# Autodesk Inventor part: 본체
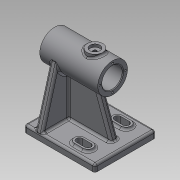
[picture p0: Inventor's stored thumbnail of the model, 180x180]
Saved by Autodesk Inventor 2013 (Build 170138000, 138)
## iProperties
Created: 2019-10
Part Number: 본체
Material: 일반
Document SubType Name: Modeling
Designer: Administrator
Density: 1 g/cm^3
Author: Administrator
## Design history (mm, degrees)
sketch "스케치1"
  geometry: L1 (-50, 43)-(50, 43); L2 (50, 43)-(50, -43); L3 (50, -43)-(-50, -43); L4 (-50, -43)-(-50, 43); L5 (-50, 43)-(50, -43); L6 (50, 43)-(-50, -43); 1 further point
  constraints: 12 end point, 2 midpoint, 2 parallel, 1 horizontal, 1 perpendicular
  dimensions: "d0" = 100 distance of L1.start L1.end; "d2" = 86 distance of L1.end L2.end
extrude "돌출1" new body sketch "스케치1" distance "d3" = 10; taper "d4" = 0 deg
sketch "스케치2"
  geometry: L1 (50, 0)-(-50, 0) reference; L2 (-32, 86)-(-32, 107); L3 (-32, 107)-(50, 107); L4 (50, 107)-(50, 86); L5 (-32, 86)-(50, 86); 2 further points
  constraints: 8 end point, 2 perpendicular, 1 midpoint, 1 parallel, 1 vertical alignment
  dimensions: "d9" = 82 distance of L2.end L3.end; "d10" = 42 diameter of L3 L5; "d11" = 172 diameter of L1 L5
revolve "회전1" sketch "스케치2" stored, may be unused: angle "d12" = 90 deg
sketch "스케치3"
  geometry: L1 (50, 10)-(50, 0) reference; L2 (50, 0)-(-50, 0) reference; L3 (-50, 0)-(-50, 10) reference; L4 (-50, 10)-(50, 10) reference; L5 (50, 65)-(-32, 65) reference; L6 (-32, 65)-(-32, 107) reference; L7 (-32, 107)-(50, 107) reference; L8 (50, 107)-(50, 65) reference; L9 (-32, 86)-(50, 86); L10 (-32, 100.5)-(30, 100.5); L11 (30, 100.5)-(30, 97.5); L12 (30, 97.5)-(50, 97.5); 1 further point
  constraints: 8 end point, 2 midpoint, 2 perpendicular, 2 point on line, 1 parallel
  dimensions: "d13" = 23 diameter of L12 L9; "d15" = 29 diameter of L10 L9; "d16" = 62 distance of L10.start L10.end
revolve "회전2" sketch "스케치3" stored, may be unused: angle "d17" = 90 deg
node "작업 평면1"
sketch "스케치4"
  geometry: L1 (-50, -43)-(-50, 43) reference; L2 (-32, -21)-(-32, 21) reference; C1 r 11 at (-7, 0); 2 further points
  constraints: 1 centre point, 1 horizontal alignment, 1 midpoint
  dimensions: "d20" = 22 diameter of C1; "d21" = 25 distance from line of L2 C1.centre
extrude "돌출2" join sketch "스케치4" stored distance "d22" = 10; taper "d23" = 0 deg
sketch "스케치5"
  geometry: C1 r 11 at (0, 0) reference
hole "구멍1" sketch "스케치5" at (0, 0) diameter "d24" = 4.917; stored, may be unused: countersink angle "d28" = 90 deg, drill point angle "d30" = 118 deg; dims "d25" = 6, "d26" = 14, "d27" = 4, "d29" = 8
sketch "스케치6"
  geometry: C1 r 14.5 at (0, 0) reference; 2 further points
  constraints: 1 horizontal alignment
  dimensions: "d31" = 18 distance of C1.centre point (-18, 0)
hole "구멍2" sketch "스케치6" at (-18, 0) diameter "d32" = 2.459; stored, may be unused: countersink angle "d36" = 90 deg, drill point angle "d38" = 118 deg; dims "d33" = 8, "d34" = 14, "d35" = 4, "d37" = 10
sketch "스케치7"
  geometry: C1 r 11.5 at (0, 0) reference; 2 further points
  constraints: 1 vertical alignment
  dimensions: "d42" = 18 distance of C1.centre point (0, 18)
hole "구멍3" sketch "스케치7" at (0, 18) diameter "d43" = 2.459; stored, may be unused: countersink angle "d47" = 90 deg, drill point angle "d49" = 118 deg; dims "d44" = 8, "d45" = 14, "d46" = 4, "d48" = 10
fillet "모깎기1" dims "d53" = 3
node "작업 평면2"
sketch "스케치9"
  geometry: L1 (10, 83)-(10, 3) reference; L2 (7, 0)-(0, 0) reference; L3 (0, 0)-(0, 86) reference; L4 (0, 86)-(7, 86) reference; L5 (7, 86)-(86, 64); L6 (7, 0)-(86, 22); C1 r 11.5 at (86, 43) reference; A1 r 3 centre (7, 83) between (10, 83) and (7, 86) reference; A2 r 3 centre (7, 3) between (7, 0) and (10, 3) reference; A3 r 21 centre (86, 43) between (86, 64) and (86, 22) reference; 1 further point
  constraints: 4 end point, 2 point on circle, 2 vertical alignment
extrude "돌출3" join sketch "스케치9" distance "d55" = 10; taper "d56" = 0 deg
sketch "스케치10"
  geometry: L1 (-32, 107)-(-18, 107) reference; L2 (-18, 107)-(-18, 110) reference; L3 (-18, 110)-(-14, 110) reference; L4 (-14, 110)-(-14, 106) reference; L5 (-14, 106)-(-9.459, 106) reference; L6 (-9.459, 106)-(-9.459, 100.5) reference; L7 (-9.459, 100.5)-(-32, 100.5) reference; L8 (-32, 100.5)-(-32, 102.77) reference; L9 (-32, 102.77)-(-22, 102.77) reference; L10 (-22, 102.77)-(-21.261, 104) reference; L11 (-21.261, 104)-(-22, 105.229) reference; L12 (-22, 105.229)-(-32, 105.229) reference; L13 (-32, 105.229)-(-32, 107) reference; L14 (50, 97.5)-(30, 97.5) reference; L15 (30, 97.5)-(30, 100.5) reference; L16 (30, 100.5)-(-4.542, 100.5) reference; L17 (-4.542, 100.5)-(-4.542, 106) reference; L18 (-4.542, 106)-(0, 106) reference; L19 (0, 106)-(0, 110) reference; L20 (0, 110)-(4, 110) reference; L21 (4, 110)-(4, 107) reference; L22 (4, 107)-(50, 107) reference; L23 (50, 107)-(50, 105.229) reference; L24 (50, 105.229)-(40, 105.229) reference; L25 (40, 105.229)-(39.261, 104) reference; L26 (39.261, 104)-(40, 102.77) reference; L27 (40, 102.77)-(50, 102.77) reference; L28 (50, 102.77)-(50, 97.5) reference; L29 (-47, 10)-(25, 10) reference; L30 (25, 10)-(25, 65) reference; L31 (25, 65)-(-32, 65) reference; L32 (-32, 65)-(-32, 66.77) reference; L33 (-32, 66.77)-(-22, 66.77) reference; L34 (-22, 66.77)-(-21.261, 68) reference; L35 (-21.261, 68)-(-22, 69.229) reference; L36 (-22, 69.229)-(-32, 69.229) reference; L37 (-32, 69.229)-(-32, 71.5) reference; L38 (-32, 71.5)-(30, 71.5) reference; L39 (30, 71.5)-(30, 74.5) reference; L40 (30, 74.5)-(50, 74.5) reference; L41 (50, 74.5)-(50, 69.229) reference; L42 (50, 69.229)-(40, 69.229) reference; L43 (40, 69.229)-(39.261, 68) reference; L44 (39.261, 68)-(40, 66.77) reference; L45 (40, 66.77)-(50, 66.77) reference; L46 (50, 66.77)-(50, 65) reference; L47 (50, 65)-(35, 65) reference; L48 (35, 65)-(35, 10) reference; L49 (35, 10)-(47, 10) reference; L50 (50, 7)-(50, 0) reference; L51 (50, 0)-(-50, 0) reference; L52 (-50, 0)-(-50, 7) reference; L53 (-35, 10)-(-14.982, 65); A1 r 3 centre (-47, 7) between (-47, 10) and (-50, 7) reference; A2 r 3 centre (47, 7) between (50, 7) and (47, 10) reference; 1 further point
  constraints: 2 end point, 2 point on line
  dimensions: "d57" = 15 distance from line of L52 L53.start; "d58" = 70 deg angle of L29 L53
feature "리브1" sketch "스케치10" dims "d59" = 1, "d60" = 10, "d61" = 0, "d62" = 0, "d63" = 1, "d64" = 1
sketch "스케치11"
  geometry: L1 (35, 5)-(35, -5) reference; L2 (24, -34)-(12, -34); L3 (12, -20)-(24, -20); L4 (50, -43)-(50, 43) reference; A1 r 7 centre (12, -27) between (12, -20) and (12, -34); A2 r 7 centre (24, -27) between (24, -34) and (24, -20); 1 further point
  constraints: 4 end point, 4 point on circle, 4 tangent, 2 centre point, 1 parallel, 1 perpendicular
  dimensions: "d65" = 27 vertical distance of point (0, 0) A2.centre; "d66" = 12 distance of L2.start L2.end; "d67" = 26 distance from line of L4 A2.centre; "d68" = 14 distance between parallel lines of L3 L2
extrude "돌출4" join sketch "스케치11" distance "d69" = 3; taper "d70" = 0 deg
sketch "스케치12"
  geometry: L1 (12, -34)-(24, -34) reference; L2 (24, -20)-(12, -20) reference; L3 (24, -31.5)-(12, -31.5); L4 (12, -22.5)-(24, -22.5); A1 r 7 centre (24, -27) between (24, -34) and (24, -20) reference; A2 r 7 centre (12, -27) between (12, -20) and (12, -34) reference; A3 r 4.5 centre (24, -27) between (24, -31.5) and (24, -22.5); A4 r 4.5 centre (12, -27) between (12, -22.5) and (12, -31.5); 1 further point
  constraints: 4 end point, 4 point on circle, 2 centre point, 3 other
  dimensions: "d71" = 9 distance between parallel lines of L3 L4
extrude "돌출5" cut sketch "스케치12" stored distance "d73" = 3; taper "d74" = 0 deg
fillet "모깎기2" dims "d75" = 3
chamfer "모따기1" distance "d76" = 1; stored, may be unused: second distance "d77" = 2, angle "d78" = 45 deg
chamfer "모따기2" distance "d79" = 1; stored, may be unused: second distance "d80" = 2, angle "d81" = 45 deg
fillet "모깎기3" dims "d82" = 3
fillet "모깎기4" dims "d83" = 3
fillet "모깎기5" dims "d84" = 3
fillet "모깎기6" dims "d85" = 3
fillet "모깎기7" dims "d86" = 3
fillet "모깎기8" dims "d87" = 3
fillet "모깎기9" dims "d88" = 3
node "작업 평면3"
sketch "스케치13"
  geometry: L1 (-50, 40)-(-50, -40) reference; L2 (47, 43)-(-47, 43) reference; 2 further points
  constraints: 1 other
  dimensions: "d90" = 7 distance from line of L1 point (-43, 0); "d91" = 43 distance from line of L2 point (-43, 0)
feature "엠보싱1" sketch "스케치13" dims "d0" = 100, "d2" = 86, "d92" = 0.5, "d93" = 0
node "솔리드1"
pattern_circular "원형 패턴1" dims angle "d40" = 360 deg
pattern_circular "원형 패턴2" dims angle "d51" = 360 deg
mirror "대칭1"
node "절단 모서리 투영1"
node "절단 모서리 투영2"
node "절단 모서리 투영3"
other parameters: "d54" = -15, "d89" = 4.5
